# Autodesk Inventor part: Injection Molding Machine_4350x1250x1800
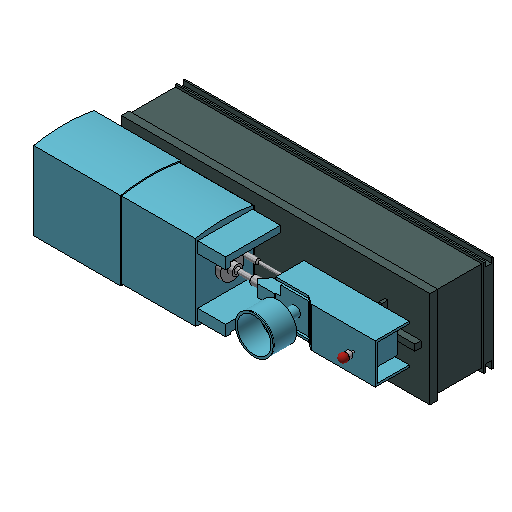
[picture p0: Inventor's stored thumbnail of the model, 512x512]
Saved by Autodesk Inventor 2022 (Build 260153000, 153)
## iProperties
RuleStatus: InUse
Created: 2012-04
Part Number: Injection Molding Machine_4350x1250x1800
Material: 一般
Document SubType Name: Modeling
Density: 1 g/cm^3
Appearance: 既定
Key Parameters: Length=4350.000 mm;Width=1250.000 mm;Height=1800.000 mm;
Author: Autodesk, Inc.
Title: Injection Molding Machine
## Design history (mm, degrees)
sketch "Sketch1"
  geometry: L1 (0, 910)-(0, -910) reference; L2 (-2800, 0)-(2800, 0) reference; L3 (-2000, 625)-(2000, 625); L4 (2000, 625)-(2000, -625); L5 (2000, -625)-(-2000, -625); L6 (-2000, -625)-(-2000, 625); L7 (2000, 329.311)-(2000, -329.311); L8 (-2000, -329.311)-(-2000, 329.311); 1 further point
  constraints: 12 end point, 3 parallel, 2 point on line, 1 horizontal, 1 perpendicular, 2 other
  dimensions: "d0" = 4000 distance of L3.start L3.end (derived); "d175" = 1250 distance of L5.end L3.start (derived)
extrude "Extrusion1" new body sketch "Sketch1" distance "d2" = 20; taper "d3" = 0 deg
sketch "Sketch2"
  geometry: L1 (2000, 625)-(-2000, 625) reference; L2 (-2000, 625)-(-2000, -625) reference; L3 (-2000, -625)-(2000, -625) reference; L4 (2000, -625)-(2000, 625) reference; L5 (-2000, 565)-(2000, 565); L6 (2000, 565)-(2000, -525); L7 (2000, -525)-(-2000, -525); L8 (-2000, -525)-(-2000, 565); 1 further point
  constraints: 8 end point, 2 collinear, 2 parallel, 1 horizontal, 1 perpendicular
  dimensions: "d6" = 60 distance between parallel lines of L1 L5; "d7" = 100 distance between parallel lines of L3 L7
extrude "Extrusion2" join sketch "Sketch2" distance "d8" = 80; taper "d9" = 0 deg
sketch "Sketch3"
  geometry: L1 (-2000, 625)-(2000, 625); L2 (2000, 625)-(2000, -625); L3 (2000, -625)-(-2000, -625); L4 (-2000, -625)-(-2000, 625); L5 (-2000, 565)-(-2000, -525) reference; L6 (2000, 625)-(-2000, 625) reference; L7 (2000, 565)-(2000, 625) reference; L8 (-2000, -625)-(2000, -625) reference; 1 further point
  constraints: 8 end point, 4 collinear, 2 parallel, 1 horizontal, 1 perpendicular
extrude "Extrusion3" join sketch "Sketch3" distance "d10" = 20; taper "d11" = 0 deg
sketch "Sketch4"
  geometry: L1 (2000, 625)-(-2000, 625) reference; L2 (-2000, -625)-(2000, -625) reference; L3 (2000, -625)-(2000, 625) reference; L4 (-432.975, 595)-(1970, 595); L5 (1970, 595)-(1970, -575); L6 (1970, -575)-(-432.975, -575); L7 (-432.975, -575)-(-432.975, 595); 1 further point
  constraints: 8 end point, 2 parallel, 1 horizontal, 1 perpendicular
  dimensions: "d12" = 30 distance between parallel lines of L3 L5; "d13" = 50 distance between parallel lines of L2 L6; "d14" = 30 distance between parallel lines of L1 L4 (= d12)
extrude "Extrusion4" join sketch "Sketch4" distance "d15" = 600 (derived); taper "d16" = 0 deg
sketch "Sketch5"
  geometry: L1 (-2000, 625)-(2000, 625); L2 (2000, 625)-(2000, -625); L3 (2000, -625)-(-2000, -625); L4 (-2000, -625)-(-2000, 625); L5 (-2000, 625)-(-2000, -625) reference; L6 (2000, 625)-(-2000, 625) reference; L7 (-2000, -625)-(2000, -625) reference; L8 (2000, -625)-(2000, 625) reference; 1 further point
  constraints: 8 end point, 4 collinear, 2 parallel, 1 horizontal, 1 perpendicular
extrude "Extrusion5" join sketch "Sketch5" distance "d17" = 100; taper "d18" = 0 deg
sketch "Sketch6"
  geometry: L1 (-432.975, -575)-(-432.975, 595) reference; L2 (-2000, 625)-(-2000, -625) reference; L3 (-2000, 595)-(-432.975, 595); L4 (-432.975, 595)-(-432.975, 555); L5 (-432.975, 555)-(-2000, 555); L6 (-2000, 555)-(-2000, 595); L7 (-2000, -560)-(-1600, -560); L8 (-1600, -560)-(-1600, -600); L9 (-1600, -600)-(-2000, -600); L10 (-2000, -600)-(-2000, -560); L11 (-432.975, 595)-(1970, 595) reference; L12 (-2000, -625)-(2000, -625) reference; 1 further point
  constraints: 16 end point, 4 parallel, 3 point on line, 2 horizontal, 2 perpendicular, 1 collinear
  dimensions: "d46" = 40 distance between parallel lines of L9 L7; "d48" = 25 distance between parallel lines of L12 L9; "d49" = 400 distance between parallel lines of L10 L8; "d50" = 40 distance between parallel lines of L5 L3
extrude "Extrusion6" join sketch "Sketch6" stored distance "d19" = 120; taper "d20" = 0 deg
sketch "Sketch7" dims "d31" = 10
  geometry: L1 (2402.975, 0)-(0, 0) reference; L2 (0, 600)-(2402.975, 600) reference; L3 (0, 0)-(0, 600) reference; L4 (30, 580)-(570.744, 580); L5 (570.744, 580)-(570.744, 20); L6 (570.744, 20)-(30, 20); L7 (30, 20)-(30, 580); L8 (1131.487, 580)-(1131.487, 20); L9 (590.744, 580)-(1131.487, 580); L10 (590.744, 20)-(590.744, 580); L11 (1131.487, 20)-(590.744, 20); L12 (1692.231, 580)-(1692.231, 20); L13 (1151.487, 580)-(1692.231, 580); L14 (1151.487, 20)-(1151.487, 580); L15 (1692.231, 20)-(1151.487, 20); L16 (2252.975, 580)-(2252.975, 20); L17 (1712.231, 580)-(2252.975, 580); L18 (1712.231, 20)-(1712.231, 580); L19 (2252.975, 20)-(1712.231, 20); 1 further point
  constraints: 32 end point, 2 horizontal, 2 parallel, 1 perpendicular, 24 other
  dimensions: "d21" = 30 distance between parallel lines of L7 L3; "d22" = 20 distance between parallel lines of L1 L6; "d23" = 20 distance between parallel lines of L4 L2; "d24" = 2402.97471 distance of L2.start L2.end (derived); "d25" = 540.74368 distance of L5.end L6.end (computed from d24); "d28" = 560.74368 distance of L4.end L8.start (computed from d25)
extrude "Extrusion7" new body sketch "Sketch7" distance "d33" = 30; taper "d34" = 0 deg
sketch "Sketch8"
  geometry: L1 (600, 1130)-(600, 0) reference; L2 (0, -50)-(600, 1130); L3 (0, -50)-(250, -50); L4 (250, -50)-(600, 638.333); 2 further points
  constraints: 6 end point, 1 coincident, 1 parallel, 1 perpendicular, 1 point on line
  dimensions: "d42" = 250 distance of L2.start L3.end
extrude "Extrusion8" join sketch "Sketch8" distance "d35" = 15; taper "d36" = 0 deg
sketch "Sketch9"
  geometry: L1 (600, 1130)-(0, -50) reference; L2 (0, -50)-(250, -50) reference; L3 (250, -50)-(600, 638.333) reference; L4 (600, 638.333)-(600, 1130) reference; L5 (16.828, -50)-(600, 1096.905); 1 further point
  constraints: 2 end point, 2 point on line, 1 parallel
  dimensions: "d37" = 15 distance between parallel lines of L1 L5
extrude "Extrusion9" join sketch "Sketch9" distance "d38" = 550; taper "d39" = 0 deg
sketch "Sketch10"
  geometry: L1 (600, 1130)-(0, -50) reference; L2 (0, -50)-(16.828, -50) reference; L3 (16.828, -50)-(600, 1096.905) reference; L4 (600, 1096.905)-(600, 1130) reference; L5 (0, -50)-(250, -50); L6 (250, -50)-(600, 638.333); L7 (600, 638.333)-(600, 1130); L8 (250, -50)-(600, 638.333) reference; 1 further point
  constraints: 6 end point, 2 perpendicular, 1 collinear, 1 parallel
extrude "Extrusion10" join sketch "Sketch10" distance "d40" = 15; taper "d41" = 0 deg
sketch "Sketch11"
  geometry: L1 (300, 0)-(410, 0); L2 (410, 0)-(410, 100); L3 (410, 100)-(300, 100); L4 (300, 100)-(300, 0); L5 (984.615, 0)-(1164.615, 0); L6 (1164.615, 0)-(1164.615, 100); L7 (1164.615, 100)-(984.615, 100); L8 (984.615, 100)-(984.615, 0); L9 (1739.231, 0)-(1849.231, 0); L10 (1849.231, 0)-(1849.231, 100); L11 (1849.231, 100)-(1739.231, 100); L12 (1739.231, 100)-(1739.231, 0); L13 (2313.846, 0)-(2423.846, 0); L14 (2423.846, 0)-(2423.846, 100); L15 (2423.846, 100)-(2313.846, 100); L16 (2313.846, 100)-(2313.846, 0); L17 (2998.462, 0)-(3108.462, 0); L18 (3108.462, 0)-(3108.462, 100); L19 (3108.462, 100)-(2998.462, 100); L20 (2998.462, 100)-(2998.462, 0); L21 (3680, 0)-(3860, 0); L22 (3860, 0)-(3860, 100); L23 (3860, 100)-(3680, 100); L24 (3680, 100)-(3680, 0); L25 (0, 100)-(4000, 100) reference; L26 (4000, 0)-(4000, 20) reference; L27 (0, 0)-(0, 20) reference; 1 further point
  constraints: 48 end point, 12 parallel, 6 collinear, 6 horizontal, 6 perpendicular, 7 other
  dimensions: "d53" = 110 distance between parallel lines of L2 L4; "d55" = 110 distance between parallel lines of L10 L12 (= d53); "d56" = 110 distance between parallel lines of L14 L16 (= d55); "d57" = 110 distance between parallel lines of L18 L20 (= d56); "d58" = 180 distance between parallel lines of L22 L24; "d59" = 180 distance between parallel lines of L6 L8 (= d58); "d242" = 140 distance between parallel lines of L26 L22; "d243" = 300 distance between parallel lines of L27 L4; "d244" = 3560 distance between parallel lines of L22 L4 (derived); "d245" = 684.61538 distance between parallel lines of L8 L4 (derived); "d247" = 684.61538 distance between parallel lines of L10 L6 (derived); "d248" = 684.61538 distance between parallel lines of L14 L12 (derived); "d250" = 684.61538 distance between parallel lines of L18 L14 (derived)
extrude "Extrusion11" join sketch "Sketch11" distance "d51" = 10; taper "d52" = 0 deg
sketch "Sketch12"
  geometry: L1 (20, 100)-(20, 0) reference; L2 (20, 100)-(100, 100) reference; L3 (100, 0)-(100, 100) reference; L4 (720, 65)-(720, 1180) reference; L5 (20, 0)-(100, 0); 1 further point
  constraints: 2 end point, 1 perpendicular
extrude "Extrusion12" join sketch "Sketch12" distance "d60" = 10; taper "d61" = 0 deg
sketch "Sketch13"
  geometry: L1 (2000, 555)-(432.975, 555) reference; L2 (432.975, 555)-(432.975, -575) reference; L3 (462.975, 355)-(942.975, 355); L4 (942.975, 355)-(942.975, -125); L5 (942.975, -125)-(462.975, -125); L6 (462.975, -125)-(462.975, 355); 1 further point
  constraints: 8 end point, 2 parallel, 2 perpendicular, 1 horizontal
  dimensions: "d63" = 480 distance of L3.end L4.end; "d65" = 30 distance between parallel lines of L2 L6; "d66" = 200 distance between parallel lines of L3 L1
extrude "Extrusion13" cut sketch "Sketch13" stored distance "d67" = 480.5; taper "d68" = 0 deg
sketch "Sketch14"
  geometry: L1 (2000, 625)-(-2000, 625) reference; L2 (-2000, -625)-(2000, -625) reference; L3 (-1550, 475)-(-270.588, 475); L4 (-270.588, 475)-(-270.588, -475); L5 (-270.588, -475)-(-1550, -475); L6 (-1550, -475)-(-1550, 475); L7 (-2000, 625)-(-2000, -625) reference; 1 further point
  constraints: 8 end point, 2 parallel, 1 horizontal, 1 perpendicular
  dimensions: "d69" = 150 distance between parallel lines of L1 L3; "d70" = 150 distance between parallel lines of L2 L5 (= d69); "d174" = 450 distance between parallel lines of L7 L6; "d254" = 1279.41176 distance of L4.end L5.end (derived)
extrude "Extrusion14" join sketch "Sketch14" distance "d71" = 20; taper "d72" = 0 deg
sketch "Sketch15"
  geometry: L1 (20, 950)-(20, 0) reference; L2 (0, 950)-(20, 950) reference; L3 (20, 968)-(20, -18); L4 (770, 968)-(770, -18); L5 (770, 968)-(20, 968); L6 (750, 951.451)-(750, -1.451); L7 (40, -1.451)-(40, 951.451); A1 r 1960 centre (395, -955.792) between (770, 968) and (20, 968); A2 r 1960 centre (395, 1905.792) between (20, -18) and (770, -18); A3 r 1940 centre (395, -955.792) between (750, 951.451) and (40, 951.451); A4 r 1940 centre (395, 1905.792) between (40, -1.451) and (750, -1.451); 1 further point
  constraints: 10 end point, 8 point on circle, 4 centre point, 3 parallel, 1 collinear, 1 equal radius, 1 horizontal, 1 point on line, 2 other
  dimensions: "d73" = 1960 radius of A1; "d75" = 18 distance from line of L2 L3.start; "d76" = 18 distance of L1.end L3.end; "d87" = 20 distance between parallel lines of L4 L6; "d88" = 20 radial gap between concentric circles of A1 A3; "d216" = 750 distance between parallel lines of L4 L1 (derived)
extrude "Extrusion15" new body sketch "Sketch15" distance "d77" = 1279.41176 (derived); taper "d78" = 0 deg
sketch "Sketch16"
  geometry: L1 (20, 968)-(20, -18) reference; L2 (770, -18)-(770, 968) reference; L3 (18, -19.647)-(18, 969.647); L4 (772, 969.647)-(772, -19.647); L5 (3, -31.956)-(3, 981.956); L6 (787, 981.956)-(787, -31.956); A1 r 1960 centre (395, 1905.792) between (20, -18) and (770, -18) reference; A2 r 1960 centre (395, -955.792) between (770, 968) and (20, 968) reference; A3 r 1962 centre (395, 1905.792) between (18, -19.647) and (772, -19.647); A4 r 1962 centre (395, -955.792) between (772, 969.647) and (18, 969.647); A5 r 1977 centre (395, 1905.792) between (3, -31.956) and (787, -31.956); A6 r 1977 centre (395, -955.792) between (787, 981.956) and (3, 981.956); 1 further point
  constraints: 8 end point, 8 point on circle, 4 centre point, 6 other
  dimensions: "d79" = 2 distance between parallel lines of L2 L4; "d80" = 15 distance between parallel lines of L5 L3; "d217" = 767 distance between parallel lines of L6 L1 (derived)
extrude "Extrusion16" join sketch "Sketch16" distance "d81" = 800 (derived); taper "d83" = 0 deg; dims "d82" = 325, "d84" = 0
sketch "Sketch17"
  geometry: L1 (18, -19.647)-(18, 969.647) reference; L2 (772, 969.647)-(772, -19.647) reference; A1 r 1962 centre (395, -955.792) between (772, 969.647) and (18, 969.647) reference; A2 r 1962 centre (395, 1905.792) between (18, -19.647) and (772, -19.647) reference; 1 further point
extrude "Extrusion17" join sketch "Sketch17" distance "d85" = 10; taper "d86" = 0 deg
sketch "Sketch18"
  geometry: L1 (1165, 1390)-(350.588, 1390); L2 (350.588, 1390)-(350.588, 1020); L3 (350.588, 1020)-(1165, 1020); L4 (1165, 1020)-(1165, 1390); L5 (1225, 1607)-(1225, 823) reference; L6 (270.588, 860)-(270.588, 1570) reference; L7 (1550, 1590)-(270.588, 1590) reference; L8 (1550, 860)-(270.588, 860) reference; 1 further point
  constraints: 8 end point, 2 parallel, 1 horizontal, 1 perpendicular
  dimensions: "d205" = 60 distance between parallel lines of L5 L4; "d206" = 80 distance between parallel lines of L6 L2; "d207" = 200 distance between parallel lines of L7 L1; "d208" = 160 distance between parallel lines of L8 L3
extrude "Extrusion18" cut sketch "Sketch18" distance "d89" = 776.5; taper "d90" = 0 deg
sketch "Sketch19"
  geometry: L1 (-40, 951.451)-(-40, -1.451) reference; L2 (-750, -1.451)-(-750, 951.451) reference; A1 r 1940 centre (-395, -955.792) between (-40, 951.451) and (-750, 951.451) reference; A2 r 1940 centre (-395, 1905.792) between (-750, -1.451) and (-40, -1.451) reference; 1 further point
extrude "Extrusion19" join sketch "Sketch19" distance "d91" = 10; taper "d92" = 0 deg
sketch "Sketch20"
  geometry: L1 (-770, 968)-(-770, -18) reference; L2 (-740, 30)-(-740, 170); L3 (-740, 170)-(-90, 170); L4 (-90, 170)-(-90, 102); L5 (-90, 102)-(-30, 102); L6 (-30, 102)-(-30, 28); L7 (-30, 28)-(-120, 28); L8 (-120, 28)-(-120, 52); L9 (-120, 52)-(-670, 52); L10 (-670, 52)-(-670, 30); L11 (-670, 30)-(-740, 30); L12 (-740, 783)-(-740, 928); L13 (-740, 928)-(-30, 928); L14 (-30, 928)-(-30, 843); L15 (-30, 843)-(-670, 843); L16 (-670, 843)-(-670, 783); L17 (-670, 783)-(-740, 783); L18 (-20, -18)-(-20, 968) reference; 1 further point
  constraints: 32 end point, 13 parallel, 3 collinear, 3 perpendicular
  dimensions: "d118" = 30 distance between parallel lines of L1 L2; "d119" = 48 distance from line of L1.end L11; "d120" = 22 distance of L9.end L10.end; "d121" = 70 distance of L10.end L2.start; "d122" = 140 distance of L2.start L2.end; "d123" = 10 distance between parallel lines of L18 L6; "d124" = 74 distance of L5.end L6.end; "d125" = 90 distance of L6.end L7.end; "d126" = 46 vertical distance of L18.start L6.end; "d127" = 60 distance of L4.end L5.end; "d128" = 40 vertical distance of L1.start L12.end; "d129" = 145 distance of L12.start L12.end; "d130" = 60 distance of L15.end L16.end
extrude "Extrusion20" join sketch "Sketch20" distance "d93" = 361.5; taper "d94" = 0 deg
sketch "Sketch21"
  geometry: L1 (-772, -19.647)-(-772, 969.647) reference; L2 (-18, 969.647)-(-18, -19.647) reference; C1 r 30 at (-395, 123.792); C2 r 30 at (-395, 826.208); A1 r 1962 centre (-395, -955.792) between (-18, 969.647) and (-772, 969.647) reference; A2 r 1962 centre (-395, 1905.792) between (-772, -19.647) and (-18, -19.647) reference; 1 further point
  constraints: 2 centre point, 1 equal radius
  dimensions: "d99" = 60 diameter of C1; "d103" = 1782 distance of A2.centre C1.centre; "d104" = 1782 distance of A1.centre C2.centre (= d103); "d180" = 754 distance between parallel lines of L2 L1 (derived); "d181" = 377 distance from line of L1 C1.centre (= 0.5 x d180); "d182" = 377 distance from line of L1 C2.centre (= d181)
extrude "Extrusion21" new body sketch "Sketch21" distance "d95" = 1200; taper "d96" = 0 deg
sketch "Sketch22"
  geometry: L1 (-195, -70)-(195, -70); L2 (195, -70)-(195, 772.416); L3 (195, 772.416)-(-195, 772.416); L4 (-195, 772.416)-(-195, -70); L5 (355, -125.243)-(355, 827.659) reference; L6 (-375, -141.792)-(-375, 844.208) reference; C1 r 30 at (0, 0) reference; C2 r 30 at (0, 702.416) reference; 1 further point
  constraints: 8 end point, 2 parallel, 1 horizontal, 1 perpendicular
  dimensions: "d105" = 70 distance from line of C1.centre L1; "d176" = 70 distance from line of L3 C2.centre (= d105); "d178" = 180 distance between parallel lines of L6 L4; "d179" = 160 distance between parallel lines of L5 L2
extrude "Extrusion22" join sketch "Sketch22" distance "d97" = 125.25; taper "d98" = 0 deg
sketch "Sketch23"
  geometry: L1 (0, 0)-(125.25, 0) reference; L2 (125.25, 390)-(125.25, 0) reference; L3 (0, 390)-(125.25, 390) reference; L4 (125.25, 302.721)-(105.25, 310); L5 (105.25, 310)-(105.25, 280); L6 (105.25, 280)-(125.25, 287.279); L7 (125.25, 102.721)-(105.25, 110); L8 (105.25, 110)-(105.25, 80); L9 (105.25, 80)-(125.25, 87.279); 1 further point
  constraints: 12 end point, 5 equal length, 4 point on line, 1 collinear, 1 perpendicular
  dimensions: "d109" = 30 distance of L4.end L5.end; "d111" = 70 deg angle of L5 L4; "d113" = 20 distance between parallel lines of L2 L5; "d114" = 80 distance from line of L3 L4.end; "d115" = 80 distance from line of L1 L8.end
extrude "Extrusion23" cut sketch "Sketch23" stored distance "d116" = 125.25; taper "d117" = 0 deg
sketch "Sketch24"
  geometry: L1 (46.254, 543.244)-(288.752, 543.244); L2 (288.752, 543.244)-(288.752, 386.475); L3 (288.752, 386.475)-(46.254, 386.475); L4 (46.254, 386.475)-(46.254, 543.244); L5 (37.301, 263.227)-(286.663, 263.227); L6 (286.663, 263.227)-(286.663, 128.776); L7 (286.663, 128.776)-(37.301, 128.776); L8 (37.301, 128.776)-(37.301, 263.227); C1 r 23.78 at (71.139, 324.924); C2 r 23.78 at (161.004, 324.924); C3 r 23.78 at (254.066, 324.924); C4 r 23.895 at (71.139, 78.825); C5 r 23.895 at (161.004, 78.825); C6 r 23.895 at (244.875, 78.825); 1 further point
  constraints: 16 end point, 6 centre point, 4 equal radius, 4 parallel, 2 horizontal, 2 perpendicular
extrude "Extrusion24" join sketch "Sketch24" distance "d131" = 10; taper "d132" = 0 deg
sketch "Sketch25"
  geometry: L1 (675, 40)-(835, 40); L2 (835, 40)-(835, -40); L3 (835, -40)-(675, -40); L4 (675, -40)-(675, 40); L5 (1415, 280)-(1455, 280); L6 (1455, 280)-(1455, -280); L7 (1455, -280)-(1415, -280); L8 (1415, -280)-(1415, 280); L9 (1455, 40)-(1885, 40); L10 (1885, 40)-(1885, -40); L11 (1885, -40)-(1455, -40); L12 (1455, -40)-(1455, 40); L13 (2000, -625)-(2000, 625) reference; L14 (0, 0)-(2365.122, 0)
  constraints: 26 end point, 6 parallel, 4 perpendicular, 3 horizontal, 1 point on line, 3 other
  dimensions: "d218" = 80 distance of L9.end L10.end; "d220" = 80 distance between parallel lines of L3 L1; "d221" = 40 distance of L6.end L7.end; "d222" = 560 distance of L7.end L5.start; "d223" = 115 distance between parallel lines of L13 L10; "d224" = 160 distance of L2.end L3.end; "d225" = 580 distance between parallel lines of L8 L2; "d226" = 430 distance of L9.start L9.end
extrude "Extrusion25" join sketch "Sketch25" distance "d133" = 80; taper "d134" = 0 deg
sketch "Sketch26"
  geometry: L1 (510.263, 200)-(1655, 200); L2 (1655, 200)-(1655, -200); L3 (1655, -200)-(510.263, -200); L4 (510.263, -200)-(510.263, 200); L5 (1415, -280)-(1455, -280) reference; L6 (1455, -280)-(1455, -40) reference; L7 (1455, 280)-(1415, 280) reference; 1 further point
  constraints: 8 end point, 2 parallel, 1 horizontal, 1 perpendicular
  dimensions: "d227" = 80 distance between parallel lines of L7 L1; "d228" = 80 distance between parallel lines of L3 L5; "d229" = 200 distance between parallel lines of L6 L2; "d255" = 1144.73684 distance between parallel lines of L2 L4 (derived)
extrude "Extrusion26" join sketch "Sketch26" distance "d135" = 400; taper "d136" = 0 deg
sketch "Sketch27"
  geometry: L1 (-510.263, 1115)-(-510.263, 1280); L2 (-510.263, 1280)-(-229.618, 1280); L3 (-229.618, 1280)-(-163.238, 1225); L4 (-163.238, 1225)-(-254.381, 1115); L5 (-254.381, 1115)-(-510.263, 1115); L6 (-510.263, 900)-(-510.263, 1300) reference; L7 (-510.263, 900)-(-1655, 900) reference; L8 (-510.263, 1300)-(-1655, 1300) reference; 1 further point
  constraints: 10 end point, 2 perpendicular, 1 collinear, 1 parallel, 1 vertical
  dimensions: "d159" = 280.64516 distance of L1.end L2.end (derived); "d161" = 255.88235 distance of L4.end L1.start (derived); "d162" = 165 distance between parallel lines of L5 L2; "d164" = 110 vertical distance of L3.end L4.end; "d213" = 20 distance between parallel lines of L8 L2
extrude "Extrusion27" join sketch "Sketch27" stored distance "d137" = 155.25; taper "d138" = 0 deg
sketch "Sketch28"
  geometry: L1 (0, 0)-(-400, 0) reference; L2 (0, -30)-(-410, -30); L3 (-410, -30)-(-410, 430); L4 (-410, 430)-(0, 430); L5 (0, 430)-(0, 460); L6 (0, 460)-(-440, 460); L7 (-440, 460)-(-440, -60); L8 (-440, -60)-(0, -60); L9 (0, -60)-(0, -30); L10 (-400, 0)-(-400, 400) reference; L11 (0, 400)-(-400, 400) reference; L12 (-430, -221.208)-(-430, 621.208) reference; 1 further point
  constraints: 16 end point, 7 parallel, 1 perpendicular
  dimensions: "d202" = 10 distance between parallel lines of L10 L3; "d231" = 30 distance between parallel lines of L1 L2; "d232" = 30 distance between parallel lines of L11 L4; "d233" = 30 distance between parallel lines of L6 L4; "d234" = 30 distance between parallel lines of L2 L8 (derived); "d296" = 30 distance between parallel lines of L3 L7 (derived)
extrude "Extrusion28" join sketch "Sketch28" distance "d139" = 155.25; taper "d141" = 0 deg; dims "d140" = 1208.33333 (derived), "d142" = 0
sketch "Sketch29"
  geometry: L1 (0, 440)-(1363.583, 440) reference; L2 (0, 0)-(0, 440) reference; L3 (0, 365)-(425, 365); L4 (425, 365)-(532.111, 440); 1 further point
  constraints: 4 end point, 2 point on line, 1 perpendicular
  dimensions: "d236" = 145 deg angle of L3 L4; "d237" = 425 distance of L3.start L3.end; "d239" = 75 distance between parallel lines of L1 L3
extrude "Extrusion29" cut sketch "Sketch29" stored distance "d143" = 155.25; taper "d144" = 0 deg
sketch "Sketch30"
  geometry: L1 (-701.086, 1265)-(-701.086, 1285); L2 (-481.667, 1800)-(-453.667, 1800); L3 (-458.667, 1781.846)-(-458.667, 1491.846); L4 (-458.667, 1491.846)-(-634.667, 1367.846); L5 (-634.667, 1367.846)-(-634.667, 1265); L6 (-634.667, 1265)-(-701.086, 1265); L7 (-481.667, 1800)-(-481.667, 1505); L8 (-481.667, 1505)-(-659.086, 1380); L9 (-659.086, 1380)-(-659.086, 1285); L10 (-659.086, 1285)-(-701.086, 1285); L11 (-2000, 820)-(2000, 820) reference; L12 (-446.667, 1265)-(-871.667, 1265) reference; L13 (-446.667, 1265)-(-446.667, 1280) reference; A1 r 12 centre (-463.34, 1792.899) between (-458.667, 1781.846) and (-453.667, 1800); 1 further point
  constraints: 20 end point, 4 perpendicular, 3 parallel, 2 point on circle, 1 centre point, 1 collinear, 1 vertical
  dimensions: "d272" = 176 horizontal distance of L3.end L4.end; "d273" = 23 distance between parallel lines of L3 L7; "d274" = 28 distance of L2.start L2.end; "d275" = 12 radius of A1; "d277" = 24 distance between parallel lines of L4 L8; "d297" = 980 distance between parallel lines of L11 L2; "d298" = 290 distance of L3.start L3.end; "d299" = 295 distance of L2.start L7.end; "d300" = 124 vertical distance of L3.end L4.end; "d301" = 125 vertical distance of L7.end L8.end; "d302" = 188 distance between parallel lines of L13 L5; "d303" = 20 distance of L1.start L1.end
revolve "Revolution1" sketch "Sketch30" stored, may be unused: angle "d145" = 90 deg
sketch "Sketch31"
  geometry: L1 (40, -1.451)-(40, 951.451) reference; L2 (750, 951.451)-(750, -1.451) reference; C1 r 38.878 at (395, 701.451); C2 r 37.699 at (395, 248.549); 1 further point
  constraints: 2 centre point
  dimensions: "d183" = 710 distance between parallel lines of L1 L2 (derived); "d184" = 355 distance from line of L2 C1.centre (= 0.5 x d183); "d185" = 355 distance from line of L2 C2.centre (= d184); "d186" = 250 vertical distance of L2.start C1.centre; "d187" = 250 vertical distance of L2.end C2.centre
extrude "Extrusion30" join sketch "Sketch31" distance "d146" = 120; taper "d147" = 0 deg
sketch "Sketch32"
  geometry: L1 (175, 130)-(-175, 130); L2 (-175, 130)-(-175, -582.902); L3 (-175, -582.902)-(175, -582.902); L4 (175, -582.902)-(175, 130); L5 (355, 250)-(355, -702.902) reference; L6 (-355, -702.902)-(-355, 250) reference; C1 r 37.699 at (0, -452.902) reference; 1 further point
  constraints: 8 end point, 2 parallel, 1 horizontal, 1 perpendicular
  dimensions: "d190" = 180 distance between parallel lines of L5 L4; "d191" = 180 distance between parallel lines of L6 L2; "d192" = 120 distance from line of L5.start L1; "d193" = 120 distance from line of L5.end L3
extrude "Extrusion31" join sketch "Sketch32" distance "d148" = 100; taper "d149" = 0 deg
sketch "Sketch33"
  geometry: L1 (-100, 0)-(-100, 350) reference; L2 (0, 0)-(-100, 0) reference; L3 (-100, 252.721)-(-80, 260); L4 (-80, 260)-(-80, 225); L5 (-80, 225)-(-100, 232.279); L6 (-100, 92.721)-(-80, 100); L7 (-80, 100)-(-80, 65); L8 (-80, 65)-(-100, 72.279); L9 (0, 350)-(-100, 350) reference; 1 further point
  constraints: 12 end point, 4 point on line, 3 equal length, 2 collinear, 1 perpendicular
  dimensions: "d194" = 70 deg angle of L4 L3; "d195" = 70 deg angle of L4 L5 (= d194); "d196" = 35 distance of L3.end L4.end; "d198" = 20 distance between parallel lines of L1 L4; "d199" = 90 distance from line of L9 L3.end; "d200" = 65 distance from line of L2 L7.end
extrude "Extrusion32" cut sketch "Sketch33" stored distance "d150" = 100; taper "d151" = 0 deg
sketch "Sketch34"
  geometry: L1 (567.025, 652.386)-(1059.412, 652.386); L2 (1059.412, 652.386)-(1059.412, 160); L3 (1059.412, 160)-(567.025, 160); L4 (567.025, 160)-(567.025, 652.386); L5 (1269.412, 0)-(1269.412, 952.902) reference; L6 (0, 0)-(1269.412, 0) reference; L7 (567.025, 539.784)-(567.025, -148.549) reference; 1 further point
  constraints: 8 end point, 2 parallel, 2 perpendicular, 1 collinear, 1 horizontal
  dimensions: "d240" = 210 distance between parallel lines of L5 L2; "d241" = 160 distance between parallel lines of L6 L3
extrude "Extrusion33" cut sketch "Sketch34" stored distance "d152" = 100; taper "d153" = 0 deg
sketch "Sketch35"
  geometry: L1 (-370, 18.185)-(-370, -1.896) reference; L2 (0, 20.101)-(0, 0) reference; A1 r 1960 centre (-195, 1950.276) between (-370, -1.896) and (0, 0) reference; A2 r 1955 centre (-195, 1950.276) between (-370, 3.124) and (0, 5.025); A3 r 1946 centre (-195, 1950.276) between (-370, 12.16) and (0, 14.07); 4 further points
  constraints: 4 point on circle, 4 point on line, 2 centre point, 2 concentric, 1 other
  dimensions: "d156" = 5 radial gap between concentric circles of A2 A1; "d157" = 6 dimension on A3
extrude "Extrusion34" new body sketch "Sketch35" stored distance "d154" = 100; taper "d155" = 0 deg
sketch "Sketch36"
  geometry: L1 (-1519.423, 1340)-(-1519.423, 1383.115); L2 (-1519.423, 1383.115)-(-1488.075, 1393.564); L3 (-1488.075, 1393.564)-(-1488.075, 1439.168); L4 (-1488.075, 1439.168)-(-1500.922, 1439.168); L5 (-1500.922, 1439.168)-(-1500.922, 1442.881); L6 (-1500.922, 1442.881)-(-1488.002, 1442.881); L7 (-1532.911, 1531.41)-(-1532.911, 1340); L8 (-1532.911, 1340)-(-1519.423, 1340); L9 (-1532.911, 1531.41)-(-1489.062, 1531.41); L10 (-978.778, 1340)-(-1810.25, 1340) reference; A1 r 55.655 centre (-1532.911, 1475.755) between (-1488.002, 1442.881) and (-1532.911, 1531.41); 1 further point
  constraints: 18 end point, 4 parallel, 3 perpendicular, 2 point on circle, 1 centre point, 1 collinear, 1 tangent, 1 vertical
revolve "Revolution2" sketch "Sketch36" stored, may be unused: angle "d158" = 90 deg
sketch "Sketch37"
  geometry: L1 (-254.381, 1180)-(270.588, 1180); L2 (270.588, 1180)-(270.588, 1332.439); L3 (270.588, 1332.439)-(202.413, 1332.439); L4 (202.413, 1332.439)-(202.413, 1247.751); L5 (202.413, 1247.751)-(135.109, 1247.751); L6 (135.109, 1247.751)-(135.109, 1221.125); L7 (135.109, 1221.125)-(105.599, 1210.388); L8 (105.599, 1210.388)-(-69.391, 1210.388); L9 (-69.391, 1210.388)-(-69.391, 1225); L10 (-79.391, 1235)-(-254.381, 1235); L11 (-254.381, 1235)-(-254.381, 1180); L12 (-254.381, 1115)-(-510.263, 1115) reference; L13 (270.588, 1560)-(270.588, 910) reference; A1 r 10 centre (-79.391, 1225) between (-69.391, 1225) and (-79.391, 1235); 2 further points
  constraints: 22 end point, 8 parallel, 3 point on line, 2 point on circle, 2 tangent, 1 centre point, 1 collinear, 1 horizontal, 1 perpendicular
  dimensions: "d166" = 10 radius of A1; "d201" = 65 distance between parallel lines of L12 L1; "d251" = 55 distance of L10.end L1.start; "d252" = 152.43902 distance between parallel lines of L1 L3 (derived); "d256" = 524.96904 distance of L1.start L1.end (derived); "d257" = 174.98968 distance of L10.start L10.end (derived); "d258" = 174.98968 distance of L7.end L8.end (derived); "d259" = 67.30372 distance of L4.end L5.end (derived); "d260" = 84.68835 distance of L3.end L4.end (derived)
revolve "Revolution3" sketch "Sketch37" stored, may be unused: angle "d165" = 90 deg
sketch "Sketch38"
  geometry: L1 (30, 580)-(30, 20) reference; L2 (570.744, 580)-(30, 580) reference; L3 (590.744, 580)-(590.744, 20) reference; L4 (790.744, 316.077)-(670.744, 316.077); L5 (670.744, 316.077)-(730.744, 420); L6 (730.744, 420)-(790.744, 316.077); L7 (780.351, 322.077)-(681.136, 322.077); L8 (681.136, 322.077)-(730.744, 408); L9 (730.744, 408)-(780.351, 322.077); L10 (1131.487, 580)-(590.744, 580) reference; C1 r 42.5 at (125, 380); 3 further points
  constraints: 12 end point, 1 centre point, 1 coincident, 1 horizontal, 1 parallel, 14 other
  dimensions: "d169" = 85 diameter of C1; "d171" = 95 distance from line of L1 C1.centre; "d172" = 200 distance from line of C1.centre L2; "d211" = 6 distance between parallel lines of L5 L8; "d212" = 120 distance of L4.start L4.end; "d214" = 80 distance from line of L3 L4.end; "d215" = 160 distance from line of L10 L5.end
extrude "Extrusion35" join sketch "Sketch38" distance "d167" = 1; taper "d168" = 0 deg
sketch "Sketch39"
  geometry: L1 (-510.263, 1000)-(-274.121, 1000); L2 (-274.121, 1000)-(-274.121, 968); L3 (-274.121, 968)-(80.811, 968); L4 (80.811, 968)-(100.838, 984); L5 (100.838, 984)-(270.588, 984); L6 (270.588, 984)-(270.588, 950); L7 (270.588, 950)-(-510.263, 950); L8 (-510.263, 950)-(-510.263, 1000); L9 (-510.263, 900)-(-1655, 900) reference; L10 (-510.263, 900)-(-510.263, 1300) reference; L11 (270.588, 1560)-(270.588, 910) reference; 2 further points
  constraints: 16 end point, 5 parallel, 2 collinear, 1 horizontal, 1 perpendicular
  dimensions: "d204" = 50 distance between parallel lines of L9 L7; "d261" = 50 distance between parallel lines of L7 L1; "d262" = 18 distance between parallel lines of L7 L3; "d263" = 34 distance between parallel lines of L7 L5; "d264" = 780.85139 distance of L6.end L7.end (derived); "d265" = 354.93245 distance of L2.end L3.end (derived); "d266" = 169.7503 distance of L4.end L5.end (derived)
revolve "Revolution4" sketch "Sketch39" stored, may be unused: angle "d203" = 90 deg
sketch "Sketch40"
  geometry: L1 (425, 365)-(0, 365) reference; L2 (0, 0)-(0, 365) reference; L3 (0, 0)-(1363.583, 0) reference; L4 (532.111, 440)-(1363.583, 440) reference; L5 (300, 250)-(630, 250); L6 (630, 250)-(630, 220); L7 (630, 220)-(300, 220); L8 (300, 220)-(300, 250); C1 r 15 at (80, 295); C2 r 15 at (80, 70); C3 r 15 at (830, 290); C4 r 15 at (830, 150); 1 further point
  constraints: 8 end point, 4 centre point, 3 equal radius, 2 parallel, 1 horizontal, 1 perpendicular
  dimensions: "d280" = 30 diameter of C1; "d282" = 70 distance from line of L1 C1.centre; "d283" = 80 distance from line of C1.centre L2; "d284" = 80 distance from line of L2 C2.centre (derived); "d285" = 70 distance from line of L3 C2.centre (derived); "d286" = 150 distance from line of L3 C4.centre; "d287" = 750 horizontal distance of C4.centre C2.centre; "d288" = 750 horizontal distance of C1.centre C3.centre (derived); "d289" = 150 distance from line of L4 C3.centre; "d290" = 30 distance of L5.end L6.end; "d291" = 330 distance of L5.start L5.end; "d292" = 220 distance between parallel lines of L3 L7; "d293" = 300 distance between parallel lines of L2 L8
extrude "Extrusion36" cut sketch "Sketch40" distance "d294" = 10; taper "d295" = 0 deg
sketch "Sketch41"
  geometry: L1 (1131.487, 580)-(590.744, 580) reference; L2 (1131.487, 20)-(1131.487, 580) reference; L3 (1089.487, 395)-(1119.487, 395); L4 (1119.487, 395)-(1119.487, 275); L5 (1119.487, 275)-(1089.487, 275); L6 (1089.487, 275)-(1089.487, 395); L7 (2210.975, 395)-(2240.975, 395); L8 (2240.975, 395)-(2240.975, 275); L9 (2240.975, 275)-(2210.975, 275); L10 (2210.975, 275)-(2210.975, 395); L11 (2252.975, 20)-(2252.975, 580) reference; 1 further point
  constraints: 16 end point, 4 parallel, 3 collinear, 2 horizontal, 2 perpendicular
  dimensions: "d305" = 120 distance of L5.end L3.start; "d307" = 30 distance of L3.start L3.end; "d308" = 12 distance between parallel lines of L2 L4; "d309" = 185 distance between parallel lines of L1 L3; "d310" = 12 distance between parallel lines of L11 L8
extrude "Extrusion37" cut sketch "Sketch41" distance "d311" = 20; taper "d312" = 0 deg
node "Landing Surface"
node "Insertion Point1"
body "Solid1"
body "Solid2"
body "Solid3"
body "Solid4"
body "Solid5"
feature "耀䁁"
